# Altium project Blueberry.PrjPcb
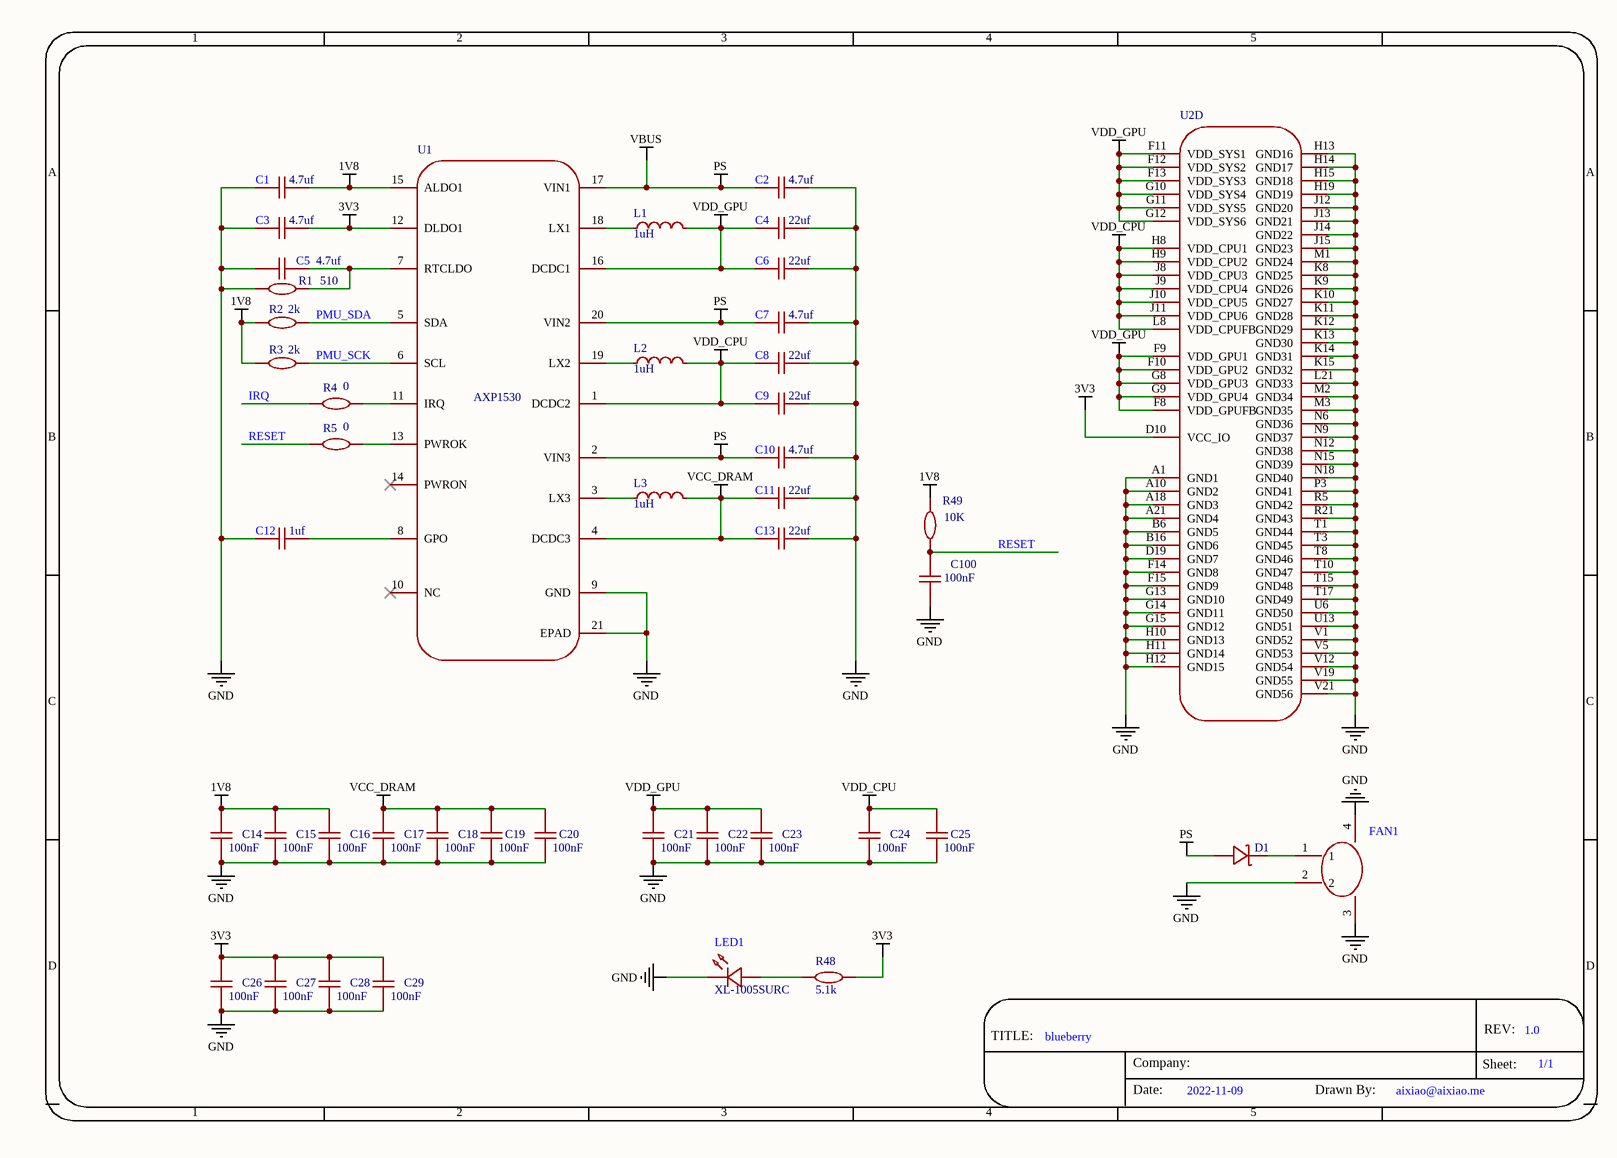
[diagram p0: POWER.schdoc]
4 sheets, 211 parts. Net scope: global (net labels, ports and power ports of the same name join across sheets).
Board file: Blueberry.PcbDoc
Sheets:
  POWER.schdoc
  PLL-IO.schdoc
  DRAM.schdoc
  IO.schdoc

## Sheet POWER.schdoc
size 302 x 215 mm; Symbol: Sheet_A4; Device: Sheet_A4; @Project Name: blueberry; REV: 1.0; Date: 2022-11-09; Sheet: 1/1; Draw By: aixiao@aixiao.me; SheetNumber: 1; SheetTotal: 4

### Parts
C1  value 4.7uf  [C0402-NSK]  (hidden comment: CAP_0402)
C2  value 4.7uf  [C0603 NSK]  (hidden comment: CAP_0603)
C3  value 4.7uf  [C0402-NSK]  (hidden comment: CAP_0402)
C4  value 22uf  [C0603 NSK]  (hidden comment: CAP_0603)
C5  value 4.7uf  [C0402-NSK]  (hidden comment: CAP_0402)
C6  value 22uf  [C0603 NSK]  (hidden comment: CAP_0603)
C7  value 4.7uf  [C0603 NSK]  (hidden comment: CAP_0603)
C8  value 22uf  [C0603 NSK]  (hidden comment: CAP_0603)
C9  value 22uf  [C0603 NSK]  (hidden comment: CAP_0603)
C10  value 4.7uf  [C0603 NSK]  (hidden comment: CAP_0603)
C11  value 22uf  [C0603 NSK]  (hidden comment: CAP_0603)
C12  value 1uf  [C0402-NSK]  (hidden comment: CAP_0402)
C13  value 22uf  [C0603 NSK]  (hidden comment: CAP_0603)
C14  value 100nF  [C0402-NSK]  (hidden comment: CAP_0402)
C15  value 100nF  [C0402-NSK]  (hidden comment: CAP_0402)
C16  value 100nF  [C0402-NSK]  (hidden comment: CAP_0402)
C17  value 100nF  [C0402-NSK]  (hidden comment: CAP_0402)
C18  value 100nF  [C0402-NSK]  (hidden comment: CAP_0402)
C19  value 100nF  [C0402-NSK]  (hidden comment: CAP_0402)
C20  value 100nF  [C0402-NSK]  (hidden comment: CAP_0402)
C21  value 100nF  [C0402-NSK]  (hidden comment: CAP_0402)
C22  value 100nF  [C0402-NSK]  (hidden comment: CAP_0402)
C23  value 100nF  [C0402-NSK]  (hidden comment: CAP_0402)
C24  value 100nF  [C0402-NSK]  (hidden comment: CAP_0402)
C25  value 100nF  [C0402-NSK]  (hidden comment: CAP_0402)
C26  value 100nF  [C0402-NSK]  (hidden comment: CAP_0402)
C27  value 100nF  [C0402-NSK]  (hidden comment: CAP_0402)
C28  value 100nF  [C0402-NSK]  (hidden comment: CAP_0402)
C29  value 100nF  [C0402-NSK]  (hidden comment: CAP_0402)
C100  value 100nF  [C0402-NSK]  (hidden comment: CAP_0402)
D1  B5819WS  [SOD-323_L1.8-W1.3-LS2.5-NSK]  (value not drawn)
FAN1  0533980271  [CONN-SMD_2P-P1.25_053398-0X71]  (value not drawn)
L1  value 1uH  [IND-SMD_L2.0-W1.6_1]  (hidden comment: CKCS201610-2.2uH/M_2)
L2  value 1uH  [IND-SMD_L2.0-W1.6_1]  (hidden comment: CKCS201610-2.2uH/M_2)
L3  value 1uH  [IND-SMD_L2.0-W1.6_1]  (hidden comment: CKCS201610-2.2uH/M_2)
LED1  XL-1005SURC  [LED0402-R-RD_RED]
R1  value 510  [R0402-NSK_2]  (hidden comment: Res_0402)
R2  value 2k  [R0402-NSK_2]  (hidden comment: Res_0402)
R3  value 2k  [R0402-NSK_2]  (hidden comment: Res_0402)
R4  value 0  [R0402-NSK_2]  (hidden comment: Res_0402)
R5  value 0  [R0402-NSK_2]  (hidden comment: Res_0402)
R48  value 5.1k  [R0402-NSK_2]  (hidden comment: Res_0402)
R49  value 10K  [R0402-NSK_2]  (hidden comment: Res_0402)
U1  AXP1530  [WQFN-20_L3.0-W3.0-P0.40-BL-EP]
U2  Allwinner_H616  [BGA284P65B1200_1400H125]  (value not drawn)  (part D of 4)

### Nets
1V8: C1.2 C14.2 C15.2 C16.2 R2.1 R3.1 R49.2 U1.15(ALDO1)
3V3: C3.2 C26.2 C27.2 C28.2 C29.2 R48.2 U1.12(DLDO1) U2.D10(VCC_IO)  [project net VDD33]
GND: C1.1 C2.2 C3.1 C4.2 C5.1 C6.2 C7.2 C8.2 C9.2 C10.2 C11.2 C12.1 C13.2 C14.1 C15.1 C16.1 C17.1 C18.1 C19.1 C20.1 C21.1 C22.1 C23.1 C24.1 C25.1 C26.1 C27.1 C28.1 C29.1 C100.1 FAN1.2 FAN1.3 FAN1.4 LED1.2(A) R1.1 U1.9(GND) U1.21(EPAD) U2.A1(GND1) U2.A10(GND2) U2.A18(GND3) U2.A21(GND4) U2.B6(GND5) U2.B16(GND6) U2.D19(GND7) U2.F14(GND8) U2.F15(GND9) U2.G13(GND10) U2.G14(GND11) U2.G15(GND12) U2.H10(GND13) U2.H11(GND14) U2.H12(GND15) U2.H13(GND16) U2.H14(GND17) U2.H15(GND18) U2.H19(GND19) U2.J12(GND20) U2.J13(GND21) U2.J14(GND22) U2.J15(GND23) U2.K8(GND25) U2.K9(GND26) U2.K10(GND27) U2.K11(GND28) U2.K12(GND29) U2.K13(GND30) U2.K14(GND31) U2.K15(GND32) U2.L21(GND33) U2.M1(GND24) U2.M2(GND34) U2.M3(GND35) U2.N6(GND36) U2.N9(GND37) U2.N12(GND38) U2.N15(GND39) U2.N18(GND40) U2.P3(GND41) U2.R5(GND42) U2.R21(GND43) U2.T1(GND44) U2.T3(GND45) U2.T8(GND46) U2.T10(GND47) U2.T15(GND48) U2.T17(GND49) U2.U6(GND50) U2.U13(GND51) U2.V1(GND52) U2.V5(GND53) U2.V12(GND54) U2.V19(GND55) U2.V21(GND56)
VBUS: C2.1 C7.1 C10.1 D1.2(A) U1.2(VIN3) U1.17(VIN1) U1.20(VIN2)  [also labelled PS]
VCC_DRAM: C11.1 C13.1 C17.2 C18.2 C19.2 C20.2 L3.2 U1.4(DCDC3)
VDD_CPU: C8.1 C9.1 C24.2 C25.2 L2.2 U1.1(DCDC2) U2.H8(VDD_CPU1) U2.H9(VDD_CPU2) U2.J8(VDD_CPU3) U2.J9(VDD_CPU4) U2.J10(VDD_CPU5) U2.J11(VDD_CPU6) U2.L8(VDD_CPUFB)
VDD_GPU: C4.1 C6.1 C21.2 C22.2 C23.2 L1.2 U1.16(DCDC1) U2.F8(VDD_GPUFB) U2.F9(VDD_GPU1) U2.F10(VDD_GPU2) U2.F11(VDD_SYS1) U2.F12(VDD_SYS2) U2.F13(VDD_SYS3) U2.G8(VDD_GPU3) U2.G9(VDD_GPU4) U2.G10(VDD_SYS4) U2.G11(VDD_SYS5) U2.G12(VDD_SYS6)
IRQ: R4.1
PMU_SCK: R3.2 U1.6(SCL)
PMU_SDA: R2.2 U1.5(SDA)
RESET: C100.2 R5.1 R49.1
NetC5_2: C5.2 R1.2 U1.7(RTCLDO)
NetC12_2: C12.2 U1.8(GPO)
NetD1_1: D1.1(K) FAN1.1
NetL1_1: L1.1 U1.18(LX1)
NetL2_1: L2.1 U1.19(LX2)
NetL3_1: L3.1 U1.3(LX3)
NetLED1_1: LED1.1(K) R48.1
NetR4_2: R4.2 U1.11(IRQ)
NetR5_2: R5.2 U1.13(PWROK)

Not connected (* = marked no-connect by the designer): U1 10(NC)* 14(PWRON)*

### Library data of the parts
C1 C3 C5 C12 C14-C29 C100 = CAP_0402: Symbol: C1210X7R475K630NT; Convert to PCB: yes
C2 C4 C6-C11 C13 = CAP_0603: Symbol: C1210X7R475K630NT; Convert to PCB: yes
D1 = B5819WS: Manufacturer: CJ（江苏长电/长晶）; Symbol: B5819WS_C22624; Add into BOM: yes; Reverse Voltage (Vr): 40V; Average Rectified Current (Io): 1A; Forward Voltage (Vf@If): 600mV@1A
FAN1 = 0533980271: Manufacturer: MOLEX; Add into BOM: yes; Pitch: 1.25mm; Pins Structure: 1x2P; Number of PINs Per Row: 2; Gender: 公型插针
L1-L3 = CKCS201610-2.2uH/M_2: Manufacturer: CENKER(岑科); Symbol: CKCS201610-2.2UH/M-N; Add into BOM: yes; Tolerance: ±20%; Rated Current: 1.1A; DC Resistance (DCR): 264mΩ
LED1 = XL-1005SURC: Manufacturer: XINGLIGHT(成兴光); Add into BOM: yes; Emitted Color: 红灯; Lens Color: 无色透明; Dominant Wavelength: 620nm; Peak Wavelength: 625nm; Color Temperature: 6000K~7000K; Forward Current: 25mA; Power Dissipation: 55mW; Viewing Angle: 120°; Mounting Sytle: 正贴
R1-R5 R48 R49 = Res_0402: Symbol: 电阻; Convert to PCB: yes
U1 = AXP1530: Add into BOM: yes; PCB Footprint: QFN21P40B300_300H78
U2 = Allwinner_H616: Symbol: H616-BGA-190823; Convert to PCB: yes

## Sheet PLL-IO.schdoc
size 302 x 215 mm; Symbol: Sheet_A4; Device: Sheet_A4; @Project Name: blueberry; REV: 1.0; Date: 2022-11-09; Sheet: 1/1; Draw By: aixiao@aixiao.me; @Page No: 2; @Page Count: 4; @Schematic Name: blueberry; @Board Name: blueberry; @Update Date: 2024-05-07; @Page Name: PLL-IO; @Create Time: 08:49:38; @Update Time: 11:45:56; @Create Date: 2023-10-26; SheetNumber: 2; SheetTotal: 4
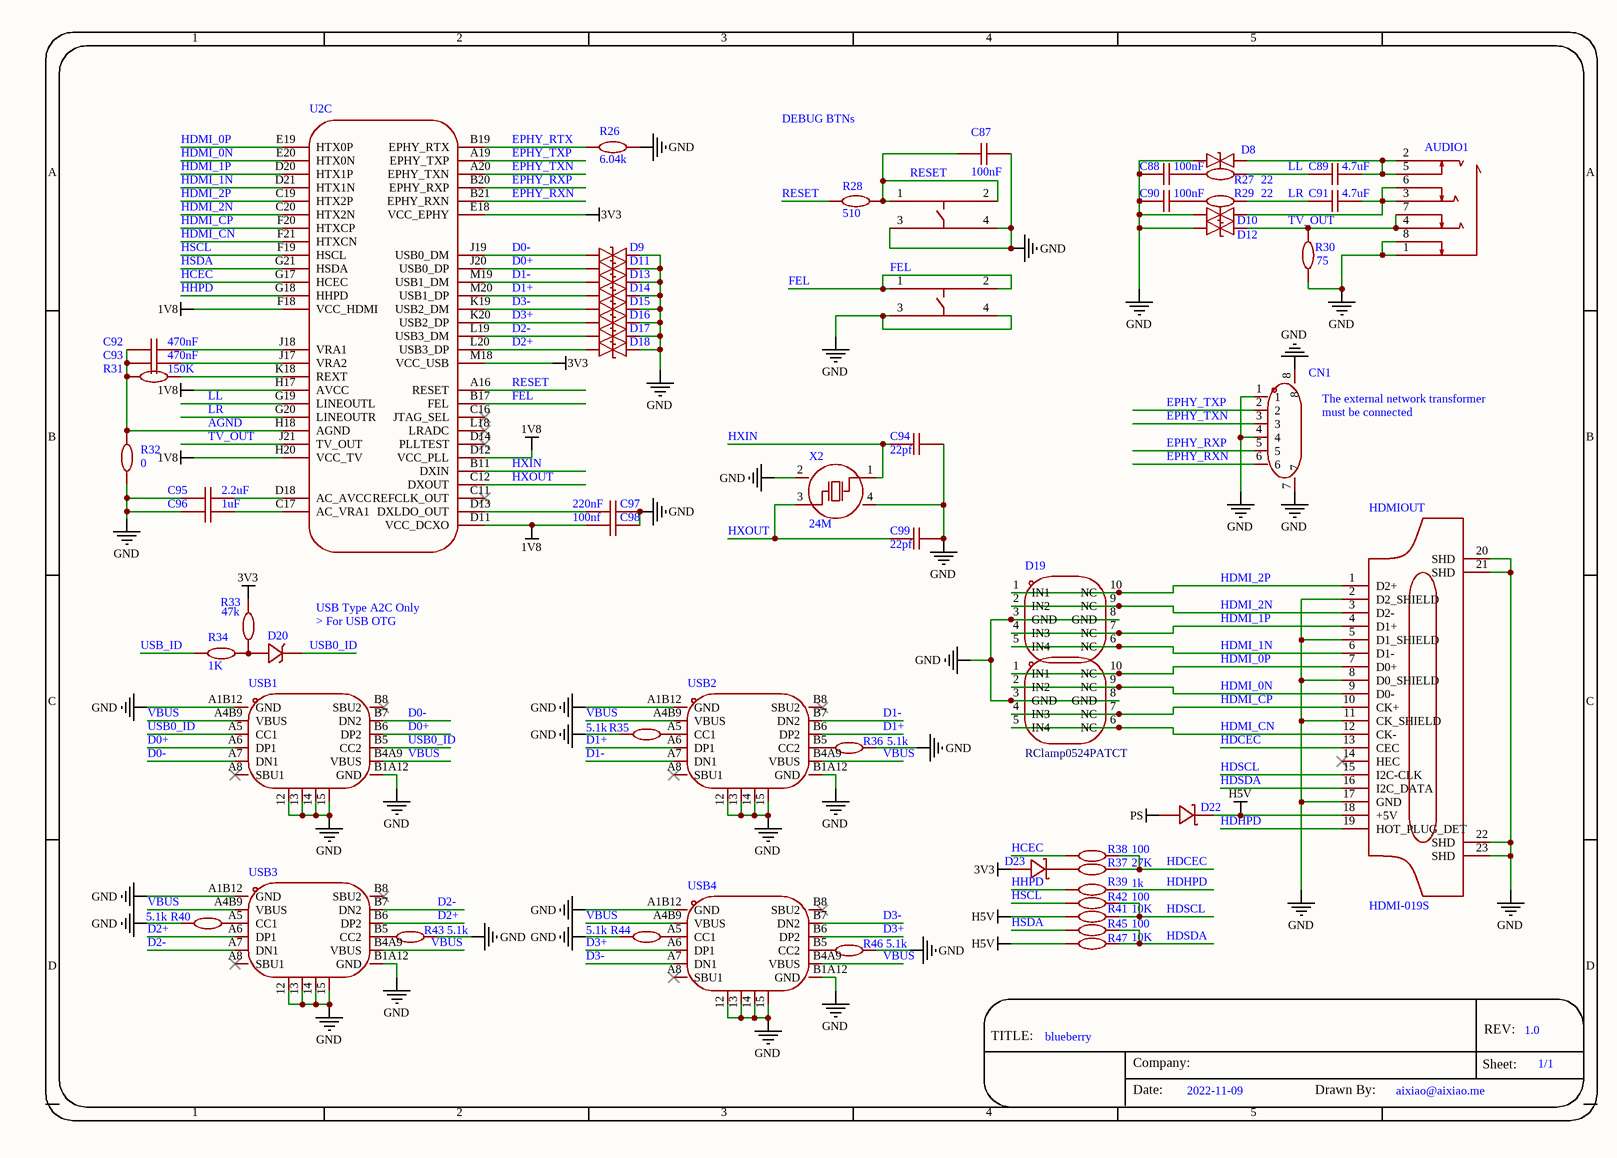
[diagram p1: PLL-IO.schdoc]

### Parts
AUDIO1  PJ-3930-8A  [AUDIO-TH_PJ-3930-8A]  (value not drawn)
C87  value 100nF  [C0402-NSK]  (hidden comment: FN15X104K250PNG)
C88  value 100nF  [C0402-NSK]  (hidden comment: CAP_0402)
C89  value 4.7uF  [C0402-NSK]  (hidden comment: CAP_0402)
C90  value 100nF  [C0402-NSK]  (hidden comment: CAP_0402)
C91  value 4.7uF  [C0402-NSK]  (hidden comment: CAP_0402)
C92  value 470nF  [C0402-NSK]  (hidden comment: CAP_0402)
C93  value 470nF  [C0402-NSK]  (hidden comment: CAP_0402)
C94  value 22pf  [C0402-NSK]  (hidden comment: CAP_0402)
C95  value 2.2uF  [C0402-NSK]  (hidden comment: CAP_0402)
C96  value 1uF  [C0402-NSK]  (hidden comment: CAP_0402)
C97  value 220nF  [C0402-NSK]  (hidden comment: CAP_0402)
C98  value 100nf  [C0402-NSK]  (hidden comment: CAP_0402)
C99  value 22pf  [C0402-NSK]  (hidden comment: CAP_0402)
CN1  532610671  [CONN-SMD_6P-P1.25_53261-0671]  (value not drawn)
D8  0402ESDA-05N  [D0402]  (value not drawn)
D9  0402ESDA-05N  [D0402]  (value not drawn)
D10  0402ESDA-05N  [D0402]  (value not drawn)
D11  0402ESDA-05N  [D0402]  (value not drawn)
D12  0402ESDA-05N  [D0402]  (value not drawn)
D13  0402ESDA-05N  [D0402]  (value not drawn)
D14  0402ESDA-05N  [D0402]  (value not drawn)
D15  0402ESDA-05N  [D0402]  (value not drawn)
D16  0402ESDA-05N  [D0402]  (value not drawn)
D17  0402ESDA-05N  [D0402]  (value not drawn)
D18  0402ESDA-05N  [D0402]  (value not drawn)
D19  RClamp0524PATCT  [SLP2510P8_L2.5-W1.0-P0.50-BL]
D20  1N5819-SOD523  [SOD-523_L1.2-W0.8-LS1.6-FD]  (value not drawn)
D21  RClamp0524PATCT  [SLP2510P8_L2.5-W1.0-P0.50-BL]  (value not drawn)
D22  B5819WS  [SOD-323_L1.8-W1.3-LS2.5-NSK]  (value not drawn)
D23  B5819WS  [SOD-323_L1.8-W1.3-LS2.5-NSK]  (value not drawn)
FEL  PTS810SJM250SMTRLFS  [KEY-SMD_4P-L4.2-W3.2-P2.20-LS4.6]  (value not drawn)
HDMIOUT  HDMI-019S  [HDMI-SMD_HDMI-019S]
R26  value 6.04k  [R0402-NSK_2]  (hidden comment: Res_0402)
R27  value 22  [R0402-NSK_2]  (hidden comment: Res_0402)
R28  value 510  [R0402-NSK_2]  (hidden comment: TR0402D10K0Q1025Z)
R29  value 22  [R0402-NSK_2]  (hidden comment: Res_0402)
R30  value 75  [R0402-NSK_2]  (hidden comment: Res_0402)
R31  value 150K  [R0402-NSK_2]  (hidden comment: Res_0402)
R32  value 0  [R0402-NSK_2]  (hidden comment: Res_0402)
R33  value 47k  [R0402-NSK_2]  (hidden comment: Res_0402)
R34  value 1K  [R0402-NSK_2]  (hidden comment: Res_0402)
R35  value 5.1k  [R0402-NSK_2]  (hidden comment: Res_0402)
R36  value 5.1k  [R0402-NSK_2]  (hidden comment: Res_0402)
R37  value 27K  [R0402-NSK_2]  (hidden comment: Res_0402)
R38  value 100  [R0402-NSK_2]  (hidden comment: Res_0402)
R39  value 1k  [R0402-NSK_2]  (hidden comment: Res_0402)
R40  value 5.1k  [R0402-NSK_2]  (hidden comment: Res_0402)
R41  value 10K  [R0402-NSK_2]  (hidden comment: Res_0402)
R42  value 100  [R0402-NSK_2]  (hidden comment: Res_0402)
R43  value 5.1k  [R0402-NSK_2]  (hidden comment: Res_0402)
R44  value 5.1k  [R0402-NSK_2]  (hidden comment: Res_0402)
R45  value 100  [R0402-NSK_2]  (hidden comment: Res_0402)
R46  value 5.1k  [R0402-NSK_2]  (hidden comment: Res_0402)
R47  value 10K  [R0402-NSK_2]  (hidden comment: Res_0402)
RESET  PTS810SJM250SMTRLFS  [KEY-SMD_4P-L4.2-W3.2-P2.20-LS4.6]  (value not drawn)
U2  Allwinner_H616  [BGA284P65B1200_1400H125]  (value not drawn)  (part C of 4)
USB1  TYPEC-304-BCP16  [USB-C-SMD_TYPEC-304-BCP16-1]  (value not drawn)
USB2  TYPEC-304-BCP16  [USB-C-SMD_TYPEC-304-BCP16-1]  (value not drawn)
USB3  TYPEC-304-BCP16  [USB-C-SMD_TYPEC-304-BCP16-1]  (value not drawn)
USB4  TYPEC-304-BCP16  [USB-C-SMD_TYPEC-304-BCP16-1]  (value not drawn)
X2  24M  [OSC-SMD_4P-L2.0-W1.6-BL]

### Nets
1V8: C98.1 U2.D11(VCC_DCXO) U2.D12(VCC_PLL) U2.F18(VCC_HDMI) U2.H17(AVCC) U2.H20(VCC_TV)
3V3: D23.2(A) R33.2 U2.E18(VCC_EPHY) U2.M18(VCC_USB)  [project net VDD33]
GND: AUDIO1.1 AUDIO1.8 C87.2 C88.1 C90.1 C94.2 C95.1 C96.1 C97.2 C98.2 C99.2 CN1.1 CN1.4 CN1.7 CN1.8 D8.1 D9.2 D10.1 D11.2 D12.1 D13.2 D14.2 D15.2 D16.2 D17.2 D18.2 D19.3(GND) D19.8(GND) D21.3(GND) D21.8(GND) FEL.3 FEL.4 HDMIOUT.2(D2_SHIELD) HDMIOUT.5(D1_SHIELD) HDMIOUT.8(D0_SHIELD) HDMIOUT.11(CK_SHIELD) HDMIOUT.17(GND) HDMIOUT.20(SHD) HDMIOUT.21(SHD) HDMIOUT.22(SHD) HDMIOUT.23(SHD) R26.2 R30.1 R32.1 R35.1 R36.2 R40.1 R43.2 R44.1 R46.2 RESET.3 RESET.4 USB1.12 USB1.13 USB1.14 USB1.15 USB1.A1B12(GND) USB1.B1A12(GND) USB2.12 USB2.13 USB2.14 USB2.15 USB2.A1B12(GND) USB2.B1A12(GND) USB3.12 USB3.13 USB3.14 USB3.15 USB3.A1B12(GND) USB3.B1A12(GND) USB4.12 USB4.13 USB4.14 USB4.15 USB4.A1B12(GND) USB4.B1A12(GND) X2.2(GND) X2.4(GND)
H5V: D22.1(K) HDMIOUT.18(+5V) R41.1 R47.1
VBUS: D22.2(A) USB1.A4B9(VBUS) USB1.B4A9(VBUS) USB2.A4B9(VBUS) USB2.B4A9(VBUS) USB3.A4B9(VBUS) USB3.B4A9(VBUS) USB4.A4B9(VBUS) USB4.B4A9(VBUS)  [also labelled PS]
AGND: C92.1 C93.1 R31.1 R32.2 U2.H18(AGND)
D0+: D11.1 U2.J20(USB0_DP) USB1.A6(DP1) USB1.B6(DP2)
D0-: D9.1 U2.J19(USB0_DM) USB1.A7(DN1) USB1.B7(DN2)
D1+: D14.1 U2.M20(USB1_DP) USB2.A6(DP1) USB2.B6(DP2)
D1-: D13.1 U2.M19(USB1_DM) USB2.A7(DN1) USB2.B7(DN2)
D2+: D18.1 U2.L20(USB3_DP) USB3.A6(DP1) USB3.B6(DP2)
D2-: D17.1 U2.L19(USB3_DM) USB3.A7(DN1) USB3.B7(DN2)
D3+: D16.1 U2.K20(USB2_DP) USB4.A6(DP1) USB4.B6(DP2)
D3-: D15.1 U2.K19(USB2_DM) USB4.A7(DN1) USB4.B7(DN2)
EPHY_RTX: R26.1 U2.B19(EPHY_RTX)
EPHY_RXN: CN1.6 U2.B21(EPHY_RXN)
EPHY_RXP: CN1.5 U2.B20(EPHY_RXP)
EPHY_TXN: CN1.3 U2.A20(EPHY_TXN)
EPHY_TXP: CN1.2 U2.A19(EPHY_TXP)
FEL: FEL.1 FEL.2 U2.B17(FEL)
HCEC: R38.1 U2.G17(HCEC)
HDCEC: HDMIOUT.13(CEC) R37.2 R38.2
HDHPD: HDMIOUT.19(HOT_PLUG_DET) R39.2
HDMI_0N: D21.2(IN2) D21.9(NC) HDMIOUT.9(D0-) U2.E20(HTX0N)
HDMI_0P: D21.1(IN1) D21.10(NC) HDMIOUT.7(D0+) U2.E19(HTX0P)
HDMI_1N: D19.5(IN4) D19.6(NC) HDMIOUT.6(D1-) U2.D21(HTX1N)
HDMI_1P: D19.4(IN3) D19.7(NC) HDMIOUT.4(D1+) U2.D20(HTX1P)
HDMI_2N: D19.2(IN2) D19.9(NC) HDMIOUT.3(D2-) U2.C20(HTX2N)
HDMI_2P: D19.1(IN1) D19.10(NC) HDMIOUT.1(D2+) U2.C19(HTX2P)
HDMI_CN: D21.5(IN4) D21.6(NC) HDMIOUT.12(CK-) U2.F21(HTXCN)
HDMI_CP: D21.4(IN3) D21.7(NC) HDMIOUT.10(CK+) U2.F20(HTXCP)
HDSCL: HDMIOUT.15(I2C-CLK) R41.2 R42.2
HDSDA: HDMIOUT.16(I2C_DATA) R45.2 R47.2
HHPD: R39.1 U2.G18(HHPD)
HSCL: R42.1 U2.F19(HSCL)
HSDA: R45.1 U2.G21(HSDA)
HXIN: C94.1 U2.B11(DXIN) X2.1(OSC1)
HXOUT: C99.1 U2.C12(DXOUT) X2.3(OSC2)
LL: C89.1 R27.2 U2.G19(LINEOUTL)
LR: C91.1 R29.2 U2.G20(LINEOUTR)
RESET: R28.1 U2.A16(RESET)
TV_OUT: AUDIO1.4 AUDIO1.7 D12.2 R30.2 U2.J21(TV_OUT)
USB0_ID: D20.2(K) USB1.A5(CC1) USB1.B5(CC2)
USB_ID: R34.1
NetAUDIO1_2: AUDIO1.2 AUDIO1.5 C89.2 D8.2
NetAUDIO1_3: AUDIO1.3 AUDIO1.6 C91.2 D10.2
NetC87_1: C87.1 R28.2 RESET.1 RESET.2
NetC88_2: C88.2 R27.1
NetC90_2: C90.2 R29.1
NetC92_2: C92.2 U2.J18(VRA1)
NetC93_2: C93.2 U2.J17(VRA2)
NetC95_2: C95.2 U2.D18(AC_AVCC)
NetC96_2: C96.2 U2.C17(AC_VRA1)
NetC97_1: C97.1 U2.D13(DXLDO_OUT)
NetD20_1: D20.1(A) R33.1 R34.2
NetD23_1: D23.1(K) R37.1
NetR31_2: R31.2 U2.K18(REXT)
NetR35_2: R35.2 USB2.A5(CC1)
NetR36_1: R36.1 USB2.B5(CC2)
NetR40_2: R40.2 USB3.A5(CC1)
NetR43_1: R43.1 USB3.B5(CC2)
NetR44_2: R44.2 USB4.A5(CC1)
NetR46_1: R46.1 USB4.B5(CC2)

Not connected (* = marked no-connect by the designer): HDMIOUT 14(HEC)*; U2 C11(REFCLK_OUT)* C16(JTAG_SEL)* D14(PLLTEST)* L18(LRADC)*; USB1 A8(SBU1)* B8(SBU2)*; USB2 A8(SBU1)* B8(SBU2)*; USB3 A8(SBU1)* B8(SBU2)*; USB4 A8(SBU1)* B8(SBU2)*

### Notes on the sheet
- DEBUG BTNs
- The external network transformer
  must be connected
- (near USB1) USB Type A2C Only
  > For USB OTG

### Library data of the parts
AUDIO1 = PJ-3930-8A: Manufacturer: 韩国韩荣; Add into BOM: yes; Connector Type: 3.5mm耳机座; Current Rating (Max): 500mA; Voltage Rating (Max): 30V
C87 = FN15X104K250PNG: Manufacturer: PSA(信昌电陶); Add into BOM: yes; Tolerance: ±10%; Voltage Rated: 25V; Temperature Coefficient: X7R
C88-C99 = CAP_0402: as C1 on sheet POWER
CN1 = 532610671: Manufacturer: MOLEX; Symbol: 53261-0671; Add into BOM: yes; Pitch: 1.25mm; Pins Structure: 1x6P; Number of PINs Per Row: 6
D8-D18 = 0402ESDA-05N: Manufacturer: BORN伯恩半导体; Add into BOM: yes; Polarity: Bidirectional; Voltage - Reverse Standoff (Typ): 5V; Voltage - Clamping (Max) @ Ipp: 50V
D19 D21 = RClamp0524PATCT: Manufacturer: SEMTECH; Add into BOM: yes
D20 = 1N5819-SOD523: Add into BOM: yes
D22 D23 = B5819WS: as D1 on sheet POWER
FEL RESET = PTS810SJM250SMTRLFS: Manufacturer: C&K; Add into BOM: yes; Contact Current: 50mA; Voltage Rating (DC): 16V; Circuit: 单刀单掷; Actuator Style: 圆形按钮; Operating Force: 160gf; Pin Style: J型引脚; Switch Length: 4.2mm; Switch Width: 3.2mm; Switch Height: 2.5mm
HDMIOUT = HDMI-019S: Manufacturer: SOFNG(硕方); Add into BOM: yes; Connector Type: HDMI; Gender: 母; Current Rating (Max): 500mA
R26 R27 R29-R47 = Res_0402: Symbol: 电阻; Convert to PCB: yes
R28 = TR0402D10K0Q1025Z: Manufacturer: EVER OHMS(天二科技); Symbol: TR0402D10KQ1025; Add into BOM: yes; Tolerance: ±0.5%; Power(Watts): 63mW; Temperature Coefficient: ±25ppm/; Overload Voltage (Max): 25V
U2 = Allwinner_H616: as U2 on sheet POWER
USB1-USB4 = TYPEC-304-BCP16: Manufacturer: XUNPU; Pin Type: IN; Add into BOM: yes
X2 = SX32Y024000BC1T: Manufacturer: TKD(泰晶); Add into BOM: yes

## Sheet DRAM.schdoc
size 302 x 215 mm; Symbol: Sheet_A4; Device: Sheet_A4; @Project Name: blueberry; REV: 1.0; Date: 2022-11-09; Sheet: 1/1; Draw By: aixiao@aixiao.me; SheetNumber: 3; SheetTotal: 4
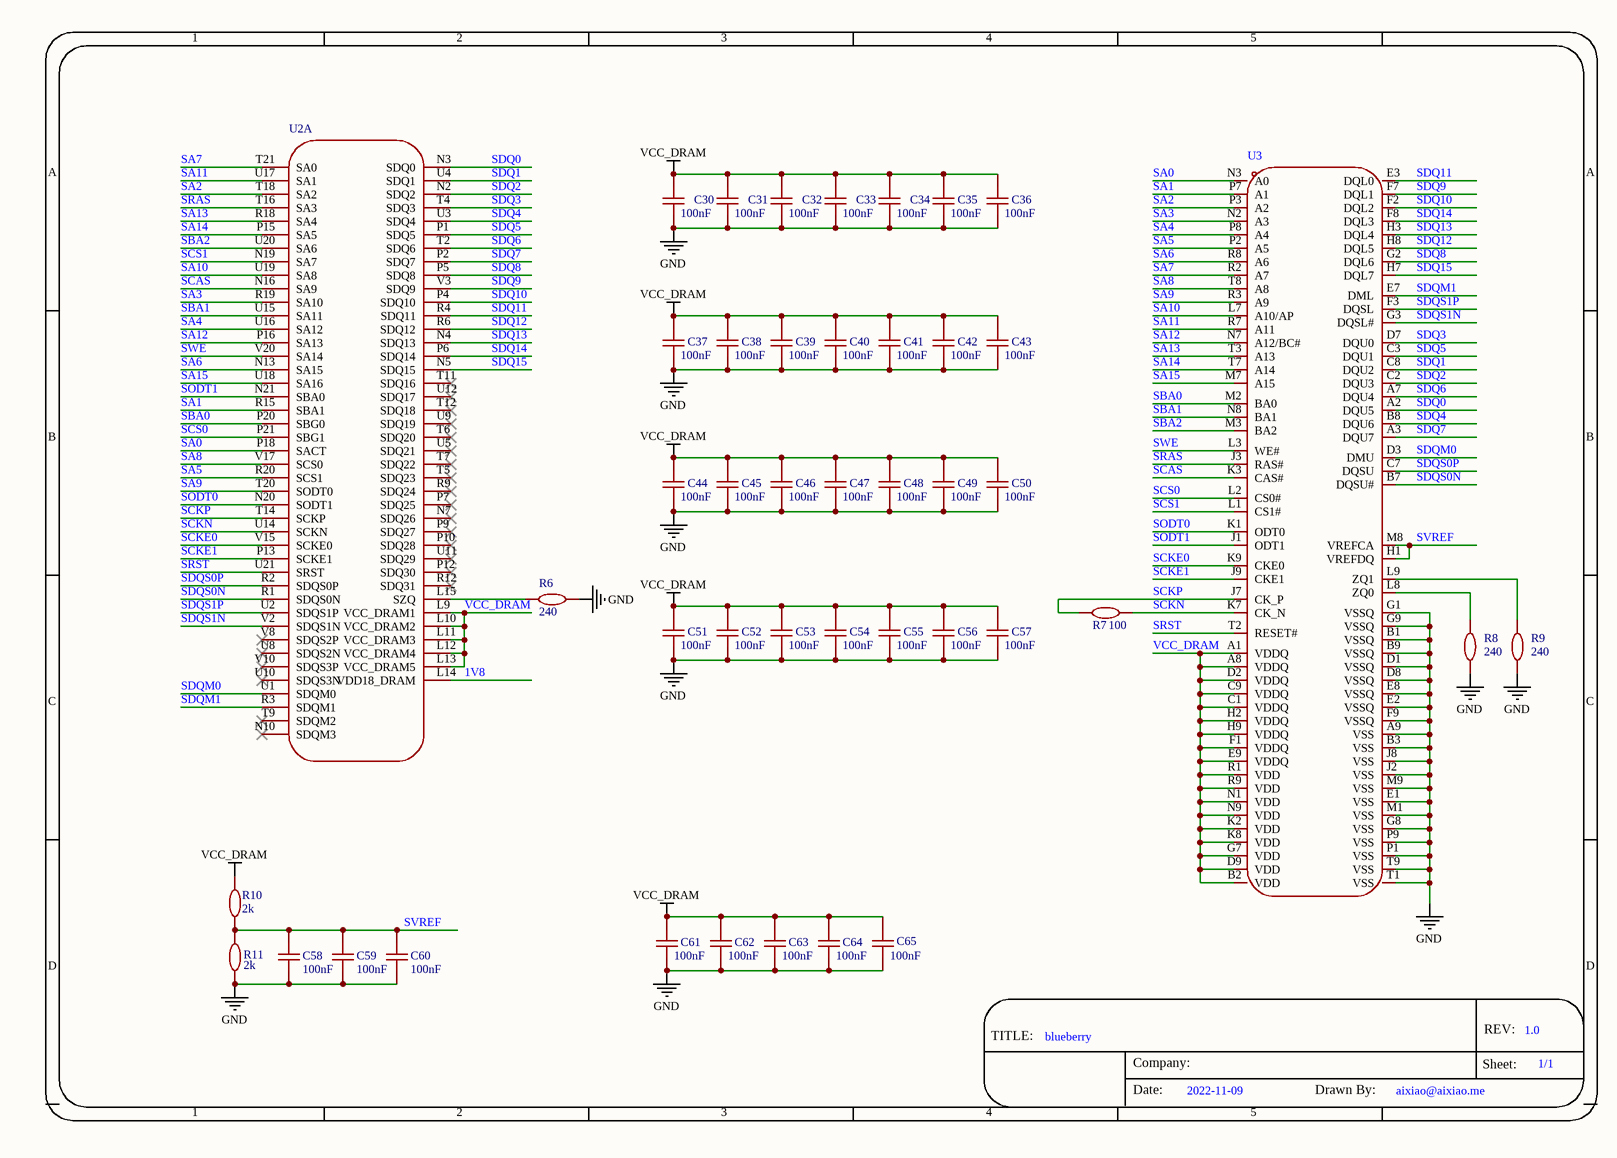
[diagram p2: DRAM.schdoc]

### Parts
C30  value 100nF  [C0402-NSK]  (hidden comment: CAP_0402)
C31  value 100nF  [C0402-NSK]  (hidden comment: CAP_0402)
C32  value 100nF  [C0402-NSK]  (hidden comment: CAP_0402)
C33  value 100nF  [C0402-NSK]  (hidden comment: CAP_0402)
C34  value 100nF  [C0402-NSK]  (hidden comment: CAP_0402)
C35  value 100nF  [C0402-NSK]  (hidden comment: CAP_0402)
C36  value 100nF  [C0402-NSK]  (hidden comment: CAP_0402)
C37  value 100nF  [C0402-NSK]  (hidden comment: CAP_0402)
C38  value 100nF  [C0402-NSK]  (hidden comment: CAP_0402)
C39  value 100nF  [C0402-NSK]  (hidden comment: CAP_0402)
C40  value 100nF  [C0402-NSK]  (hidden comment: CAP_0402)
C41  value 100nF  [C0402-NSK]  (hidden comment: CAP_0402)
C42  value 100nF  [C0402-NSK]  (hidden comment: CAP_0402)
C43  value 100nF  [C0402-NSK]  (hidden comment: CAP_0402)
C44  value 100nF  [C0402-NSK]  (hidden comment: CAP_0402)
C45  value 100nF  [C0402-NSK]  (hidden comment: CAP_0402)
C46  value 100nF  [C0402-NSK]  (hidden comment: CAP_0402)
C47  value 100nF  [C0402-NSK]  (hidden comment: CAP_0402)
C48  value 100nF  [C0402-NSK]  (hidden comment: CAP_0402)
C49  value 100nF  [C0402-NSK]  (hidden comment: CAP_0402)
C50  value 100nF  [C0402-NSK]  (hidden comment: CAP_0402)
C51  value 100nF  [C0402-NSK]  (hidden comment: CAP_0402)
C52  value 100nF  [C0402-NSK]  (hidden comment: CAP_0402)
C53  value 100nF  [C0402-NSK]  (hidden comment: CAP_0402)
C54  value 100nF  [C0402-NSK]  (hidden comment: CAP_0402)
C55  value 100nF  [C0402-NSK]  (hidden comment: CAP_0402)
C56  value 100nF  [C0402-NSK]  (hidden comment: CAP_0402)
C57  value 100nF  [C0402-NSK]  (hidden comment: CAP_0402)
C58  value 100nF  [C0402-NSK]  (hidden comment: CAP_0402)
C59  value 100nF  [C0402-NSK]  (hidden comment: CAP_0402)
C60  value 100nF  [C0402-NSK]  (hidden comment: CAP_0402)
C61  value 100nF  [C0402-NSK]  (hidden comment: CAP_0402)
C62  value 100nF  [C0402-NSK]  (hidden comment: CAP_0402)
C63  value 100nF  [C0402-NSK]  (hidden comment: CAP_0402)
C64  value 100nF  [C0402-NSK]  (hidden comment: CAP_0402)
C65  value 100nF  [C0402-NSK]  (hidden comment: CAP_0402)
R6  value 240  [R0402-NSK_2]  (hidden comment: Res_0402)
R7  value 100  [R0402-NSK_2]  (hidden comment: Res_0402)
R8  value 240  [R0402-NSK_2]  (hidden comment: Res_0402)
R9  value 240  [R0402-NSK_2]  (hidden comment: Res_0402)
R10  value 2k  [R0402-NSK_2]  (hidden comment: Res_0402)
R11  value 2k  [R0402-NSK_2]  (hidden comment: Res_0402)
U2  Allwinner_H616  [BGA284P65B1200_1400H125]  (value not drawn)  (part A of 4)
U3  H5TQ4G63EFR-RDC  [FBGA96]  (value not drawn)

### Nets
1V8: U2.L14(VDD18_DRAM)
GND: C30.1 C31.1 C32.1 C33.1 C34.1 C35.1 C36.1 C37.1 C38.1 C39.1 C40.1 C41.1 C42.1 C43.1 C44.1 C45.1 C46.1 C47.1 C48.1 C49.1 C50.1 C51.1 C52.1 C53.1 C54.1 C55.1 C56.1 C57.1 C58.1 C59.1 C60.1 C61.1 C62.1 C63.1 C64.1 C65.1 R6.2 R8.1 R9.1 R11.1 U3.A9(VSS) U3.B1(VSSQ) U3.B3(VSS) U3.B9(VSSQ) U3.D1(VSSQ) U3.D8(VSSQ) U3.E1(VSS) U3.E2(VSSQ) U3.E8(VSSQ) U3.F9(VSSQ) U3.G1(VSSQ) U3.G8(VSS) U3.G9(VSSQ) U3.J2(VSS) U3.J8(VSS) U3.M1(VSS) U3.M9(VSS) U3.P1(VSS) U3.P9(VSS) U3.T1(VSS) U3.T9(VSS)
VCC_DRAM: C30.2 C31.2 C32.2 C33.2 C34.2 C35.2 C36.2 C37.2 C38.2 C39.2 C40.2 C41.2 C42.2 C43.2 C44.2 C45.2 C46.2 C47.2 C48.2 C49.2 C50.2 C51.2 C52.2 C53.2 C54.2 C55.2 C56.2 C57.2 C61.2 C62.2 C63.2 C64.2 C65.2 R10.2 U2.L9(VCC_DRAM1) U2.L10(VCC_DRAM2) U2.L11(VCC_DRAM3) U2.L12(VCC_DRAM4) U2.L13(VCC_DRAM5) U3.A1(VDDQ) U3.A8(VDDQ) U3.B2(VDD) U3.C1(VDDQ) U3.C9(VDDQ) U3.D2(VDDQ) U3.D9(VDD) U3.E9(VDDQ) U3.F1(VDDQ) U3.G7(VDD) U3.H2(VDDQ) U3.H9(VDDQ) U3.K2(VDD) U3.K8(VDD) U3.N1(VDD) U3.N9(VDD) U3.R1(VDD) U3.R9(VDD)
SA0: U2.P18(SACT) U3.N3(A0)
SA1: U2.R15(SBA1) U3.P7(A1)
SA2: U2.T18(SA2) U3.P3(A2)
SA3: U2.R19(SA10) U3.N2(A3)
SA4: U2.U16(SA12) U3.P8(A4)
SA5: U2.R20(SCS1) U3.P2(A5)
SA6: U2.N13(SA15) U3.R8(A6)
SA7: U2.T21(SA0) U3.R2(A7)
SA8: U2.V17(SCS0) U3.T8(A8)
SA9: U2.T20(SODT0) U3.R3(A9)
SA10: U2.U19(SA8) U3.L7(A10/AP)
SA11: U2.U17(SA1) U3.R7(A11)
SA12: U2.P16(SA13) U3.N7(A12/BC#)
SA13: U2.R18(SA4) U3.T3(A13)
SA14: U2.P15(SA5) U3.T7(A14)
SA15: U2.U18(SA16) U3.M7(A15)
SBA0: U2.P20(SBG0) U3.M2(BA0)
SBA1: U2.U15(SA11) U3.N8(BA1)
SBA2: U2.U20(SA6) U3.M3(BA2)
SCAS: U2.N16(SA9) U3.K3(CAS#)
SCKE0: U2.V15(SCKE0) U3.K9(CKE0)
SCKE1: U2.P13(SCKE1) U3.J9(CKE1)
SCKN: R7.2 U2.U14(SCKN) U3.K7(CK_N)
SCKP: R7.1 U2.T14(SCKP) U3.J7(CK_P)
SCS0: U2.P21(SBG1) U3.L2(CS0#)
SCS1: U2.N19(SA7) U3.L1(CS1#)
SDQ0: U2.N3(SDQ0) U3.A2(DQU5)
SDQ1: U2.U4(SDQ1) U3.C8(DQU2)
SDQ2: U2.N2(SDQ2) U3.C2(DQU3)
SDQ3: U2.T4(SDQ3) U3.D7(DQU0)
SDQ4: U2.U3(SDQ4) U3.B8(DQU6)
SDQ5: U2.P1(SDQ5) U3.C3(DQU1)
SDQ6: U2.T2(SDQ6) U3.A7(DQU4)
SDQ7: U2.P2(SDQ7) U3.A3(DQU7)
SDQ8: U2.P5(SDQ8) U3.G2(DQL6)
SDQ9: U2.V3(SDQ9) U3.F7(DQL1)
SDQ10: U2.P4(SDQ10) U3.F2(DQL2)
SDQ11: U2.R4(SDQ11) U3.E3(DQL0)
SDQ12: U2.R6(SDQ12) U3.H8(DQL5)
SDQ13: U2.N4(SDQ13) U3.H3(DQL4)
SDQ14: U2.P6(SDQ14) U3.F8(DQL3)
SDQ15: U2.N5(SDQ15) U3.H7(DQL7)
SDQM0: U2.U1(SDQM0) U3.D3(DMU)
SDQM1: U2.R3(SDQM1) U3.E7(DML)
SDQS0N: U2.R1(SDQS0N) U3.B7(DQSU#)
SDQS0P: U2.R2(SDQS0P) U3.C7(DQSU)
SDQS1N: U2.V2(SDQS1N) U3.G3(DQSL#)
SDQS1P: U2.U2(SDQS1P) U3.F3(DQSL)
SODT0: U2.N20(SODT1) U3.K1(ODT0)
SODT1: U2.N21(SBA0) U3.J1(ODT1)
SRAS: U2.T16(SA3) U3.J3(RAS#)
SRST: U2.U21(SRST) U3.T2(RESET#)
SVREF: C58.2 C59.2 C60.2 R10.1 R11.2 U3.H1(VREFDQ) U3.M8(VREFCA)
SWE: U2.V20(SA14) U3.L3(WE#)
NetR6_1: R6.1 U2.L15(SZQ)
NetR8_2: R8.2 U3.L8(ZQ0)
NetR9_2: R9.2 U3.L9(ZQ1)

Not connected (* = marked no-connect by the designer): U2 N7(SDQ26)* N10(SDQM3)* P7(SDQ25)* P9(SDQ27)* P10(SDQ28)* P12(SDQ30)* R9(SDQ24)* R12(SDQ31)* T5(SDQ23)* T6(SDQ20)* T7(SDQ22)* T9(SDQM2)* T11(SDQ16)* T12(SDQ18)* U5(SDQ21)* U8(SDQS2N)* U9(SDQ19)* U10(SDQS3N)* U11(SDQ29)* U12(SDQ17)* V8(SDQS2P)* V10(SDQS3P)*

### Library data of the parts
C30-C65 = CAP_0402: as C1 on sheet POWER
R6-R11 = Res_0402: Symbol: 电阻; Convert to PCB: yes
U2 = Allwinner_H616: as U2 on sheet POWER
U3 = H5TQ4G63EFR-RDC: Manufacturer: HYNIX(海力士); Pin Type: IN; Add into BOM: yes

## Sheet IO.schdoc
size 429 x 307 mm; Symbol: Sheet_A3; Device: Sheet_A3; @Project Name: blueberry; REV: 1.0; Date: 2022-11-09; Sheet: 1/1; Draw By: aixiao@aixiao.me; @Page No: 4; @Page Count: 4; @Schematic Name: blueberry; @Board Name: blueberry; @Update Date: 2023-12-25; @Page Name: IO; @Create Time: 08:49:38; @Update Time: 15:31:42; @Create Date: 2023-10-26; SheetNumber: 4; SheetTotal: 4
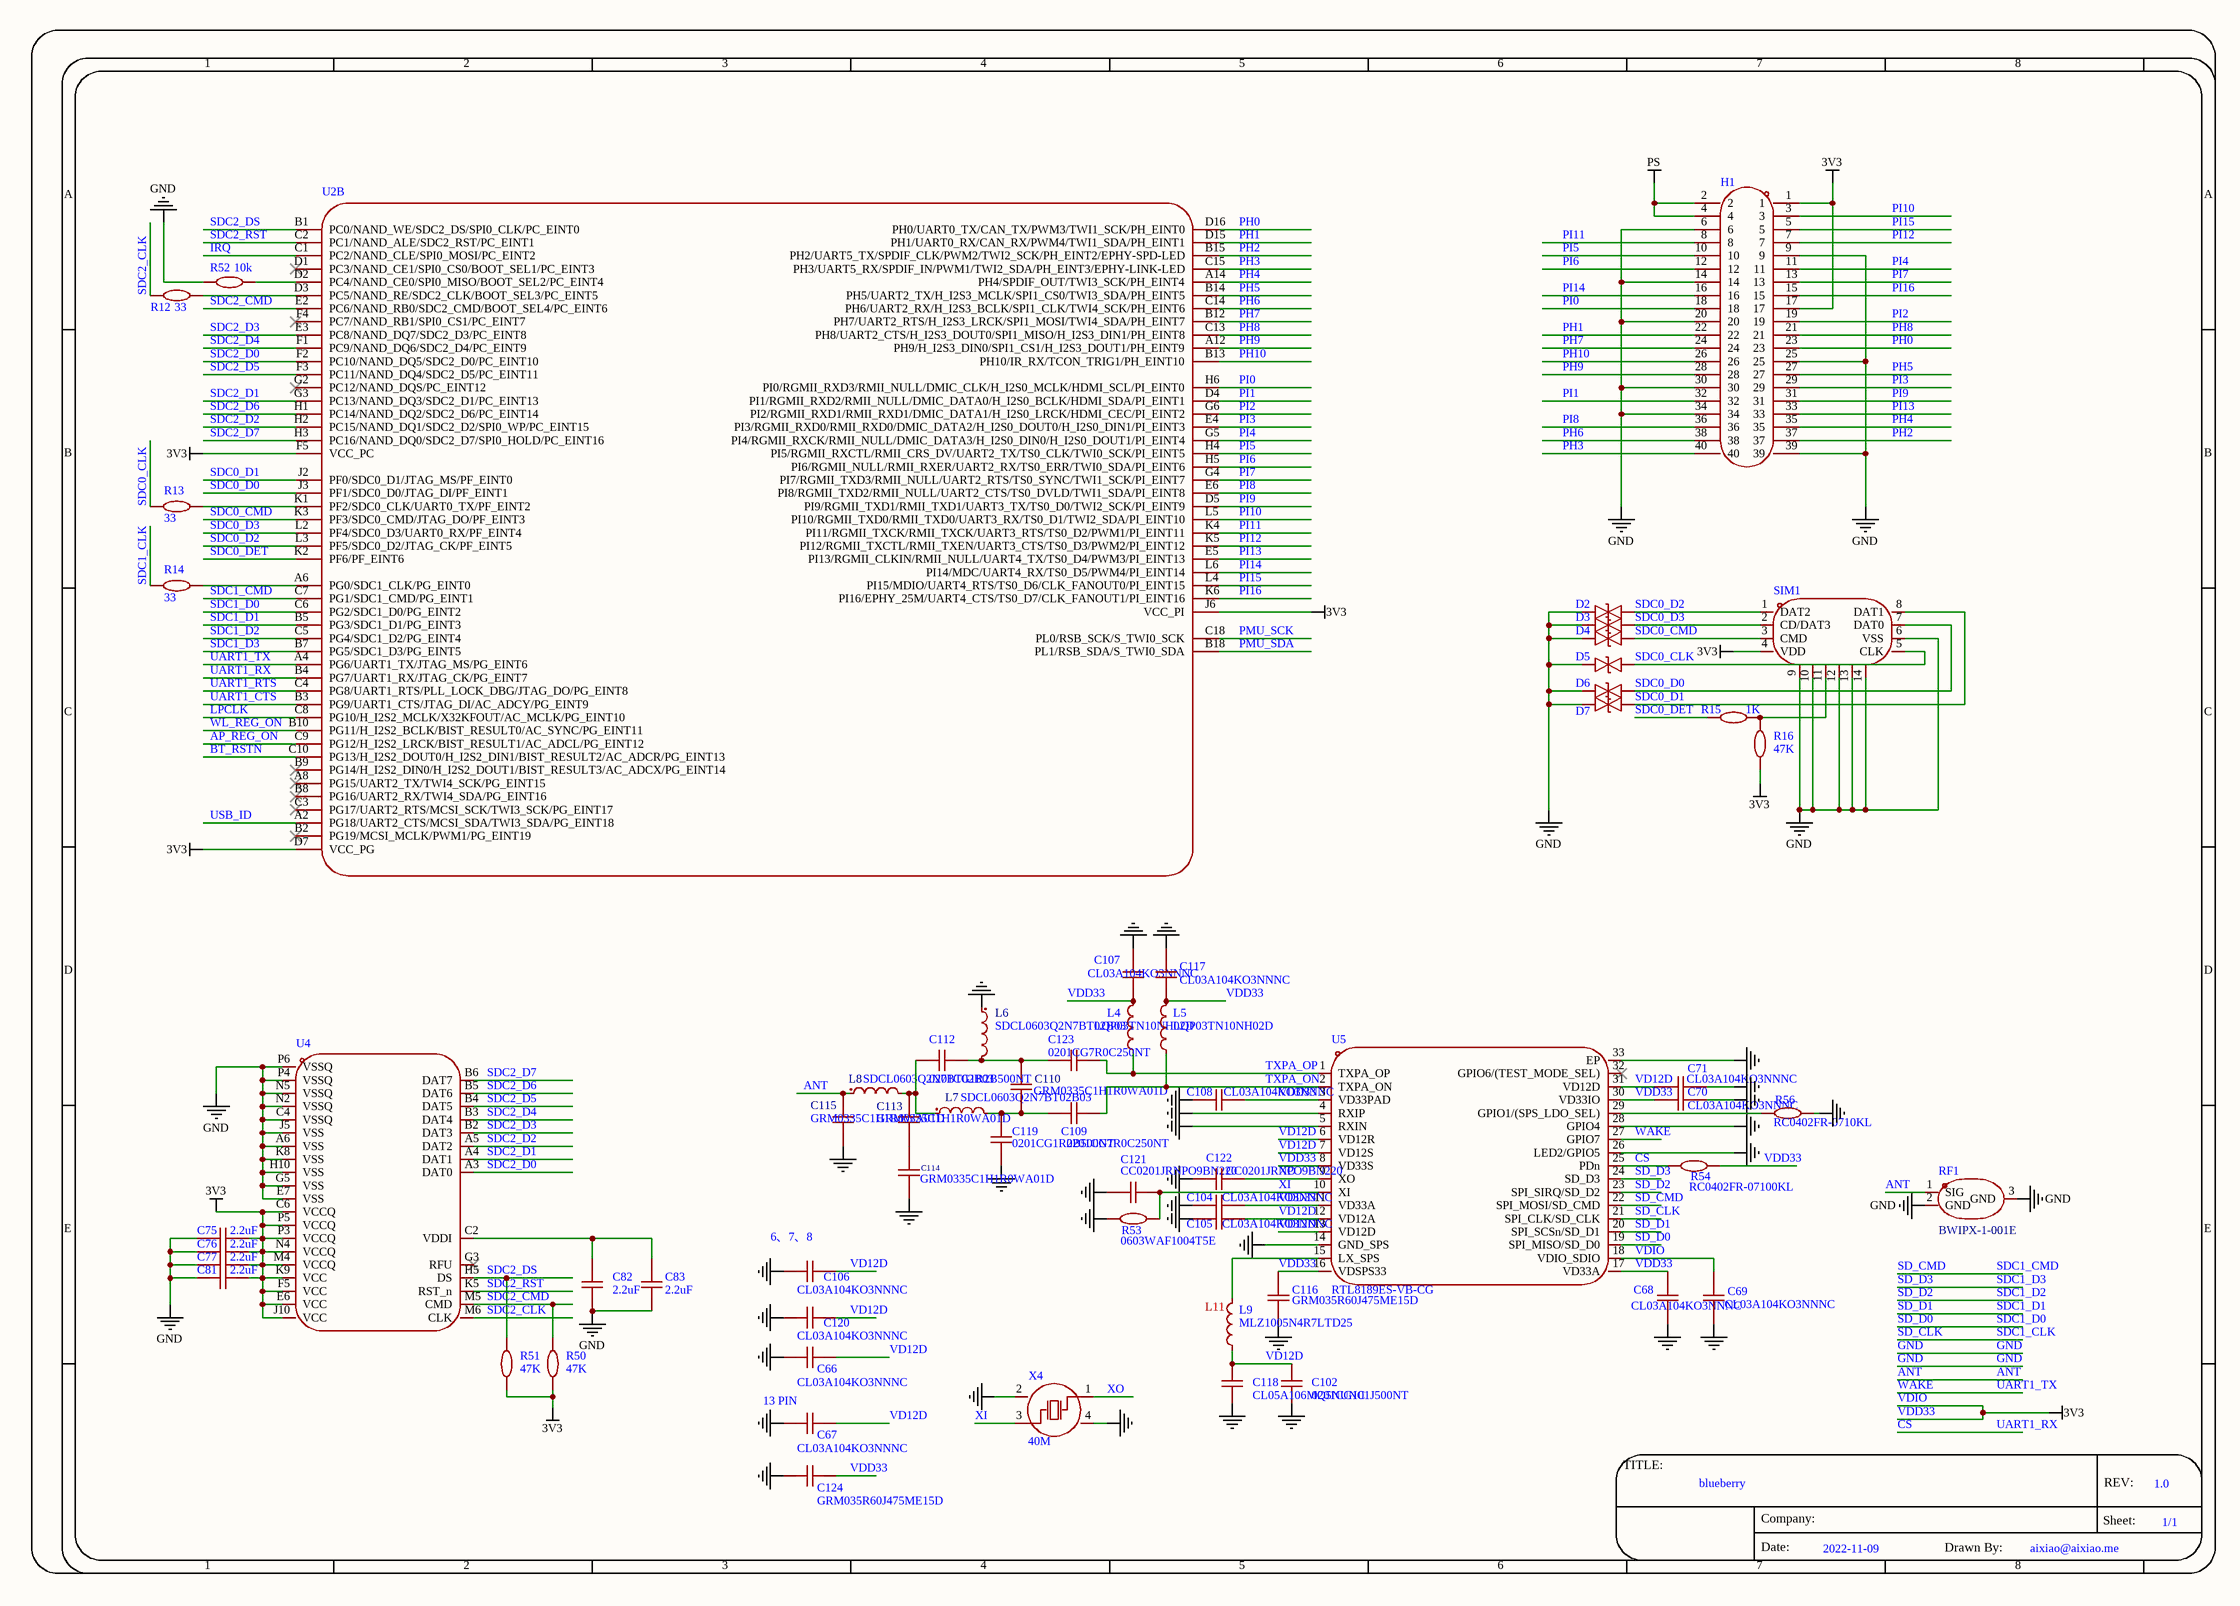
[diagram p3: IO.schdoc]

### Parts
C66  CL03A104KO3NNNC  [C0201]
C67  CL03A104KO3NNNC  [C0201]
C68  CL03A104KO3NNNC  [C0201]
C69  CL03A104KO3NNNC  [C0201]
C70  CL03A104KO3NNNC  [C0201]
C71  CL03A104KO3NNNC  [C0201]
C75  value 2.2uF  [C0402-NSK]  (hidden comment: CAP_0402)
C76  value 2.2uF  [C0402-NSK]  (hidden comment: CAP_0402)
C77  value 2.2uF  [C0402-NSK]  (hidden comment: CAP_0402)
C81  value 2.2uF  [C0402-NSK]  (hidden comment: CAP_0402)
C82  value 2.2uF  [C0402-NSK]  (hidden comment: CAP_0402)
C83  value 2.2uF  [C0402-NSK]  (hidden comment: CAP_0402)
C102  0201CG101J500NT  [C0201]
C104  CL03A104KO3NNNC  [C0201]
C105  CL03A104KO3NNNC  [C0201]
C106  CL03A104KO3NNNC  [C0201]
C107  CL03A104KO3NNNC  [C0201]
C108  CL03A104KO3NNNC  [C0201]
C109  0201CG7R0C250NT  [C0201]
C110  GRM0335C1H1R0WA01D  [C0201]
C112  0201CG1R2B500NT  [C0201]
C113  GRM0335C1H1R0WA01D  [C0201]
C114  GRM0335C1H1R0WA01D  [C0201]
C115  GRM0335C1H1R0WA01D  [C0201]
C116  GRM035R60J475ME15D  [C0201]
C117  CL03A104KO3NNNC  [C0201]
C118  CL05A106MQ5NUNC  [C0402]
C119  0201CG1R2B500NT  [C0201]
C120  CL03A104KO3NNNC  [C0201]
C121  CC0201JRNPO9BN220  [C0201]
C122  CC0201JRNPO9BN220  [C0201]
C123  0201CG7R0C250NT  [C0201]
C124  GRM035R60J475ME15D  [C0201]
D2  0402ESDA-05N  [D0402]  (value not drawn)
D3  0402ESDA-05N  [D0402]  (value not drawn)
D4  0402ESDA-05N  [D0402]  (value not drawn)
D5  0402ESDA-05N  [D0402]  (value not drawn)
D6  0402ESDA-05N  [D0402]  (value not drawn)
D7  0402ESDA-05N  [D0402]  (value not drawn)
H1  B-2100S40P-B110  [HDR-TH_40P-P2.54-V-M-R2-C20-S2.54]  (value not drawn)
L4  LQP03TN10NH02D  [L0201]
L5  LQP03TN10NH02D  [L0201]
L6  SDCL0603Q2N7BT02B03  [L0201-RD]
L7  SDCL0603Q2N7BT02B03  [L0201-RD]
L8  SDCL0603Q2N7BT02B03  [L0201-RD]
L9  MLZ1005N4R7LTD25  [L0402]
R12  value 33  [R0402-NSK_2]  (hidden comment: Res_0402)
R13  value 33  [R0402-NSK_2]  (hidden comment: Res_0402)
R14  value 33  [R0402-NSK_2]  (hidden comment: Res_0402)
R15  value 1K  [R0402-NSK_2]  (hidden comment: Res_0402)
R16  value 47K  [R0402-NSK_2]  (hidden comment: Res_0402)
R50  value 47K  [R0402-NSK_2]  (hidden comment: Res_0402)
R51  value 47K  [R0402-NSK_2]  (hidden comment: Res_0402)
R52  value 10k  [R0402-NSK_2]  (hidden comment: Res_0402)
R53  0603WAF1004T5E  [R0603]
R54  RC0402FR-07100KL  [R0402]
R56  RC0402FR-0710KL  [R0402]
RF1  BWIPX-1-001E  [IPEX-SMD_BWIPX-1-001E]
SIM1  1040310811  [SIM-SMD_8P-1040310811]  (value not drawn)
U2  Allwinner_H616  [BGA284P65B1200_1400H125]  (value not drawn)  (part B of 4)
U4  EMMC BGA153  [FBGA-153_L13.0-W11.5]  (value not drawn)
U5  RTL8189ES-VB-CG  [QFN-32_L5.0-W5.0-P0.50-TL-EP3.5]
X4  40M  [osc-smd_4p-l2.0-w1.6-bl]

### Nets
GND: C66.2 C67.2 C68.1 C69.1 C70.1 C71.1 C75.1 C76.1 C77.1 C81.1 C82.1 C83.1 C102.1 C104.2 C105.2 C106.2 C107.1 C108.2 C114.1 C115.1 C116.1 C117.1 C118.1 C119.2 C120.2 C121.2 C122.2 C124.2 D2.1 D3.1 D4.1 D5.1 D6.1 D7.1 H1.6 H1.9 H1.14 H1.20 H1.25 H1.30 H1.34 H1.39 L6.1 R52.2 R53.1 R56.2 RF1.2(GND) RF1.3(GND) SIM1.6(VSS) SIM1.9 SIM1.10 SIM1.12 SIM1.13 SIM1.14 U4.A6(VSS) U4.C4(VSSQ) U4.E7(VSS) U4.G5(VSS) U4.H10(VSS) U4.J5(VSS) U4.K8(VSS) U4.N2(VSSQ) U4.N5(VSSQ) U4.P4(VSSQ) U4.P6(VSSQ) U5.4(RXIP) U5.5(RXIN) U5.14(GND_SPS) U5.26(LED2/GPIO5) U5.28(GPIO4) U5.33(EP) X4.2(GND) X4.4(GND)
PS: H1.2 H1.4  [project net VBUS]
VDD33: C68.2 C69.2 C70.2 C75.2 C76.2 C77.2 C81.2 C104.1 C107.2 C108.1 C116.2 C117.2 C124.1 H1.1 H1.17 L4.2 L5.2 R16.1 R50.1 R51.1 R54.2 SIM1.4(VDD) U2.D7(VCC_PG) U2.F5(VCC_PC) U2.J6(VCC_PI) U4.C6(VCCQ) U4.E6(VCC) U4.F5(VCC) U4.J10(VCC) U4.K9(VCC) U4.M4(VCCQ) U4.N4(VCCQ) U4.P3(VCCQ) U4.P5(VCCQ) U5.3(VD33PAD) U5.8(VD33S) U5.11(VD33A) U5.16(VDSPS33) U5.17(VD33A) U5.18(VDIO_SDIO) U5.30(VD33IO)  [also labelled 3V3, VDIO]
ANT: C115.2 L8.1 RF1.1(SIG)
AP_REG_ON: U2.C9(PG12/H_I2S2_LRCK/BIST_RESULT1/AC_ADCL/PG_EINT12)
BT_RSTN: U2.C10(PG13/H_I2S2_DOUT0/H_I2S2_DIN1/BIST_RESULT2/AC_ADCR/PG_EINT13)
CS: R54.1 U2.B4(PG7/UART1_RX/JTAG_CK/PG_EINT7) U5.25(PDn)  [also labelled UART1_RX]
IRQ: U2.C1(PC2/NAND_CLE/SPI0_MOSI/PC_EINT2)
LPCLK: U2.C8(PG10/H_I2S2_MCLK/X32KFOUT/AC_MCLK/PG_EINT10)
PH0: H1.23 U2.D16(PH0/UART0_TX/CAN_TX/PWM3/TWI1_SCK/PH_EINT0)
PH1: H1.22 U2.D15(PH1/UART0_RX/CAN_RX/PWM4/TWI1_SDA/PH_EINT1)
PH2: H1.37 U2.B15(PH2/UART5_TX/SPDIF_CLK/PWM2/TWI2_SCK/PH_EINT2/EPHY-SPD-LED)
PH3: H1.40 U2.C15(PH3/UART5_RX/SPDIF_IN/PWM1/TWI2_SDA/PH_EINT3/EPHY-LINK-LED)
PH4: H1.35 U2.A14(PH4/SPDIF_OUT/TWI3_SCK/PH_EINT4)
PH5: H1.27 U2.B14(PH5/UART2_TX/H_I2S3_MCLK/SPI1_CS0/TWI3_SDA/PH_EINT5)
PH6: H1.38 U2.C14(PH6/UART2_RX/H_I2S3_BCLK/SPI1_CLK/TWI4_SCK/PH_EINT6)
PH7: H1.24 U2.B12(PH7/UART2_RTS/H_I2S3_LRCK/SPI1_MOSI/TWI4_SDA/PH_EINT7)
PH8: H1.21 U2.C13(PH8/UART2_CTS/H_I2S3_DOUT0/SPI1_MISO/H_I2S3_DIN1/PH_EINT8)
PH9: H1.28 U2.A12(PH9/H_I2S3_DIN0/SPI1_CS1/H_I2S3_DOUT1/PH_EINT9)
PH10: H1.26 U2.B13(PH10/IR_RX/TCON_TRIG1/PH_EINT10)
PI0: H1.18 U2.H6(PI0/RGMII_RXD3/RMII_NULL/DMIC_CLK/H_I2S0_MCLK/HDMI_SCL/PI_EINT0)
PI1: H1.32 U2.D4(PI1/RGMII_RXD2/RMII_NULL/DMIC_DATA0/H_I2S0_BCLK/HDMI_SDA/PI_EINT1)
PI2: H1.19 U2.G6(PI2/RGMII_RXD1/RMII_RXD1/DMIC_DATA1/H_I2S0_LRCK/HDMI_CEC/PI_EINT2)
PI3: H1.29 U2.E4(PI3/RGMII_RXD0/RMII_RXD0/DMIC_DATA2/H_I2S0_DOUT0/H_I2S0_DIN1/PI_EINT3)
PI4: H1.11 U2.G5(PI4/RGMII_RXCK/RMII_NULL/DMIC_DATA3/H_I2S0_DIN0/H_I2S0_DOUT1/PI_EINT4)
PI5: H1.10 U2.H4(PI5/RGMII_RXCTL/RMII_CRS_DV/UART2_TX/TS0_CLK/TWI0_SCK/PI_EINT5)
PI6: H1.12 U2.H5(PI6/RGMII_NULL/RMII_RXER/UART2_RX/TS0_ERR/TWI0_SDA/PI_EINT6)
PI7: H1.13 U2.G4(PI7/RGMII_TXD3/RMII_NULL/UART2_RTS/TS0_SYNC/TWI1_SCK/PI_EINT7)
PI8: H1.36 U2.E6(PI8/RGMII_TXD2/RMII_NULL/UART2_CTS/TS0_DVLD/TWI1_SDA/PI_EINT8)
PI9: H1.31 U2.D5(PI9/RGMII_TXD1/RMII_TXD1/UART3_TX/TS0_D0/TWI2_SCK/PI_EINT9)
PI10: H1.3 U2.L5(PI10/RGMII_TXD0/RMII_TXD0/UART3_RX/TS0_D1/TWI2_SDA/PI_EINT10)
PI11: H1.8 U2.K4(PI11/RGMII_TXCK/RMII_TXCK/UART3_RTS/TS0_D2/PWM1/PI_EINT11)
PI12: H1.7 U2.K5(PI12/RGMII_TXCTL/RMII_TXEN/UART3_CTS/TS0_D3/PWM2/PI_EINT12)
PI13: H1.33 U2.E5(PI13/RGMII_CLKIN/RMII_NULL/UART4_TX/TS0_D4/PWM3/PI_EINT13)
PI14: H1.16 U2.L6(PI14/MDC/UART4_RX/TS0_D5/PWM4/PI_EINT14)
PI15: H1.5 U2.L4(PI15/MDIO/UART4_RTS/TS0_D6/CLK_FANOUT0/PI_EINT15)
PI16: H1.15 U2.K6(PI16/EPHY_25M/UART4_CTS/TS0_D7/CLK_FANOUT1/PI_EINT16)
PMU_SCK: U2.C18(PL0/RSB_SCK/S_TWI0_SCK)
PMU_SDA: U2.B18(PL1/RSB_SDA/S_TWI0_SDA)
SD_CLK: R14.1 U5.21(SPI_CLK/SD_CLK)  [also labelled SDC1_CLK]
SD_CMD: U2.C7(PG1/SDC1_CMD/PG_EINT1) U5.22(SPI_MOSI/SD_CMD)  [also labelled SDC1_CMD]
SD_D0: U2.C6(PG2/SDC1_D0/PG_EINT2) U5.19(SPI_MISO/SD_D0)  [also labelled SDC1_D0]
SD_D1: U2.B5(PG3/SDC1_D1/PG_EINT3) U5.20(SPI_SCSn/SD_D1)  [also labelled SDC1_D1]
SD_D2: U2.C5(PG4/SDC1_D2/PG_EINT4) U5.23(SPI_SIRQ/SD_D2)  [also labelled SDC1_D2]
SD_D3: U2.B7(PG5/SDC1_D3/PG_EINT5) U5.24(SD_D3)  [also labelled SDC1_D3]
SDC0_CLK: D5.2 R13.1 SIM1.5(CLK)
SDC0_CMD: D4.2 SIM1.3(CMD) U2.K3(PF3/SDC0_CMD/JTAG_DO/PF_EINT3)
SDC0_D0: D6.2 SIM1.7(DAT0) U2.J3(PF1/SDC0_D0/JTAG_DI/PF_EINT1)
SDC0_D1: D7.2 SIM1.8(DAT1) U2.J2(PF0/SDC0_D1/JTAG_MS/PF_EINT0)
SDC0_D2: D2.2 SIM1.1(DAT2) U2.L3(PF5/SDC0_D2/JTAG_CK/PF_EINT5)
SDC0_D3: D3.2 SIM1.2(CD/DAT3) U2.L2(PF4/SDC0_D3/UART0_RX/PF_EINT4)
SDC0_DET: R15.1 U2.K2(PF6/PF_EINT6)
SDC2_CLK: R12.1 U4.M6(CLK)
SDC2_CMD: R50.2 U2.E2(PC6/NAND_RB0/SDC2_CMD/BOOT_SEL4/PC_EINT6) U4.M5(CMD)
SDC2_D0: U2.F2(PC10/NAND_DQ5/SDC2_D0/PC_EINT10) U4.A3(DAT0)
SDC2_D1: U2.G3(PC13/NAND_DQ3/SDC2_D1/PC_EINT13) U4.A4(DAT1)
SDC2_D2: U2.H2(PC15/NAND_DQ1/SDC2_D2/SPI0_WP/PC_EINT15) U4.A5(DAT2)
SDC2_D3: U2.E3(PC8/NAND_DQ7/SDC2_D3/PC_EINT8) U4.B2(DAT3)
SDC2_D4: U2.F1(PC9/NAND_DQ6/SDC2_D4/PC_EINT9) U4.B3(DAT4)
SDC2_D5: U2.F3(PC11/NAND_DQ4/SDC2_D5/PC_EINT11) U4.B4(DAT5)
SDC2_D6: U2.H1(PC14/NAND_DQ2/SDC2_D6/PC_EINT14) U4.B5(DAT6)
SDC2_D7: U2.H3(PC16/NAND_DQ0/SDC2_D7/SPI0_HOLD/PC_EINT16) U4.B6(DAT7)
SDC2_DS: R51.2 U2.B1(PC0/NAND_WE/SDC2_DS/SPI0_CLK/PC_EINT0) U4.H5(DS)
SDC2_RST: U2.C2(PC1/NAND_ALE/SDC2_RST/PC_EINT1) U4.K5(RST_n)
TXPA_ON: C109.2 L5.1 U5.2(TXPA_ON)
TXPA_OP: C123.2 L4.1 U5.1(TXPA_OP)
UART1_CTS: U2.B3(PG9/UART1_CTS/JTAG_DI/AC_ADCY/PG_EINT9)
UART1_RTS: U2.C4(PG8/UART1_RTS/PLL_LOCK_DBG/JTAG_DO/PG_EINT8)
UART1_TX: U2.A4(PG6/UART1_TX/JTAG_MS/PG_EINT6) U5.27(GPIO7)  [also labelled WAKE]
USB_ID: U2.A2(PG18/UART2_CTS/MCSI_SDA/TWI3_SDA/PG_EINT18)
VD12D: C66.1 C67.1 C71.2 C102.2 C105.1 C106.1 C118.2 C120.1 L9.1 U5.6(VD12R) U5.7(VD12S) U5.12(VD12A) U5.13(VD12D) U5.31(VD12D)
WL_REG_ON: U2.B10(PG11/H_I2S2_BCLK/BIST_RESULT0/AC_SYNC/PG_EINT11)
XI: C121.1 R53.2 U5.10(XI) X4.3(OSC2)
XO: C122.1 U5.9(XO) X4.1(OSC1)
NetC82_2: C82.2 C83.2 U4.C2(VDDI)
NetC109_1: C109.1 C110.1 C119.1 L7.2
NetC110_2: C110.2 C112.1 C123.1 L6.2
NetC112_2: C112.2 C113.2 L7.1 L8.2
NetC113_1: C113.1 C114.2
NetL9_2: L9.2 U5.15(LX_SPS)
NetR12_2: R12.2 U2.D3(PC5/NAND_RE/SDC2_CLK/BOOT_SEL3/PC_EINT5)
NetR13_2: R13.2 U2.K1(PF2/SDC0_CLK/UART0_TX/PF_EINT2)
NetR14_2: R14.2 U2.A6(PG0/SDC1_CLK/PG_EINT0)
NetR15_2: R15.2 R16.2 SIM1.11
NetR52_1: R52.1 U2.D2(PC4/NAND_CE0/SPI0_MISO/BOOT_SEL2/PC_EINT4)
NetR56_1: R56.1 U5.29(GPIO1/(SPS_LDO_SEL))

Not connected (* = marked no-connect by the designer): U2 A8(PG15/UART2_TX/TWI4_SCK/PG_EINT15)* B2(PG19/MCSI_MCLK/PWM1/PG_EINT19)* B8(PG16/UART2_RX/TWI4_SDA/PG_EINT16)* B9(PG14/H_I2S2_DIN0/H_I2S2_DOUT1/BIST_RESULT3/AC_ADCX/PG_EINT14)* C3(PG17/UART2_RTS/MCSI_SCK/TWI3_SCK/PG_EINT17)* D1(PC3/NAND_CE1/SPI0_CS0/BOOT_SEL1/PC_EINT3)* F4(PC7/NAND_RB1/SPI0_CS1/PC_EINT7)* G2(PC12/NAND_DQS/PC_EINT12)*; U4 G3(RFU)*; U5 32(GPIO6/(TEST_MODE_SEL))*

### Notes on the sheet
- (near C106) 6、7、8
- (near L9) L11
- (near C67) 13 PIN

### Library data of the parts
C66-C71 C104-C108 C117 C120 = CL03A104KO3NNNC: Manufacturer: SAMSUNG(三星); Add into BOM: yes; Value: 100nF; Tolerance: ±10%; Voltage Rated: 16V; Temperature Coefficient: X5R
C75-C77 C81-C83 = CAP_0402: as C1 on sheet POWER
C102 = 0201CG101J500NT: Manufacturer: FH(风华); Add into BOM: yes; Value: 100pF; Tolerance: ±5%; Voltage Rated: 50V; Temperature Coefficient: C0G
C109 C123 = 0201CG7R0C250NT: Manufacturer: FH(风华); Add into BOM: yes; Value: 7pF; Voltage Rated: 25V; Temperature Coefficient: C0G
C110 C113-C115 = GRM0335C1H1R0WA01D: Manufacturer: muRata(村田); Value: 1pF; Add into BOM: yes; Voltage Rated: 50V; Temperature Coefficient: C0G
C112 C119 = 0201CG1R2B500NT: Manufacturer: FH(风华); Add into BOM: yes; Value: 1.2pF; Voltage Rated: 50V; Temperature Coefficient: C0G
C116 C124 = GRM035R60J475ME15D: Manufacturer: muRata(村田); Add into BOM: yes; Value: 4.7uF; Tolerance: ±20%; Voltage Rated: 6.3V; Temperature Coefficient: X5R
C118 = CL05A106MQ5NUNC: Manufacturer: SAMSUNG(三星); Add into BOM: yes; Value: 10uF; Tolerance: ±20%; Voltage Rated: 6.3V; Temperature Coefficient: X5R
C121 C122 = CC0201JRNPO9BN220: Manufacturer: YAGEO(国巨); Add into BOM: yes; Value: 22pF; Tolerance: ±5%; Voltage Rated: 50V; Temperature Coefficient: NP0
D2-D7 = 0402ESDA-05N: as D8 on sheet PLL-IO
H1 = B-2100S40P-B110: Manufacturer: Ckmtw(灿科盟); Symbol: 210S-2*20P L=11.6MMGold-plated black; Add into BOM: yes; Pitch: 2.54mm; Pin Structure: 2x20P
L4 L5 = LQP03TN10NH02D: Manufacturer: muRata(村田); Add into BOM: yes; Value: 10nH; Tolerance: ±3%; Rated Current: 250mA; DC Resistance (DCR): 700mΩ; Q @ Freq: 14@500MHz; Frequency - Self Resonant: 3.2GHz
L6-L8 = SDCL0603Q2N7BT02B03: Manufacturer: Sunlord(顺络); Value: 2.7nH; Add into BOM: yes; Rated Current: 500mA; DC Resistance (DCR): 200mΩ; Q @ Freq: 13@500MHz; Frequency - Self Resonant: 500MHz
L9 = MLZ1005N4R7LTD25: Manufacturer: TDK; Add into BOM: yes; Value: 4.7uH; Tolerance: ±20%
R12-R16 R50-R52 = Res_0402: Symbol: 电阻; Convert to PCB: yes
R53 = 0603WAF1004T5E: Manufacturer: UNI-ROYAL(厚声); Add into BOM: yes; Value: 1MΩ; Tolerance: ±1%; Power(Watts): 100mW; Temperature Coefficient: ±100ppm/℃; Overload Voltage (Max): 75V
R54 = RC0402FR-07100KL: Manufacturer: YAGEO(国巨); Add into BOM: yes; Value: 100kΩ; Tolerance: ±1%; Power(Watts): 62.5mW; Temperature Coefficient: ±100ppm/℃; Overload Voltage (Max): 50V
R56 = RC0402FR-0710KL: Manufacturer: YAGEO(国巨); Add into BOM: yes; Value: 10kΩ; Tolerance: ±1%; Power(Watts): 62.5mW; Temperature Coefficient: ±100ppm/℃; Overload Voltage (Max): 50V
RF1 = BWIPX-1-001E: Manufacturer: BATWIRELESS(蝙蝠无线); Add into BOM: yes; Connector Type: 板端; RF Series: IPEX; Interface Type: 内针; Number of Ports: 1; Impedance: 50Ω; Frequency-Max: 6GHz
SIM1 = 1040310811: Manufacturer: MOLEX; Add into BOM: yes; Card Connection Mode: 拔插式; Card Type: MicroSD卡(TF卡); Connector Type: 卡座; Maximum Body Height: 1.42mm
U2 = Allwinner_H616: as U2 on sheet POWER
U4 = EMMC BGA153: Manufacturer: Kingston(金士顿); Manufacturer Part: EMMC04G-M627-A01; Pin Type: IN; Add into BOM: yes
U5 = RTL8189ES-VB-CG: Manufacturer: REALTEK(瑞昱); Add into BOM: yes
X4 = SX32Y024000BC1T: Manufacturer: TKD(泰晶); Add into BOM: yes

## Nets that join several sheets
1V8: POWER (8 pins), PLL-IO (6 pins), DRAM (U2.L14)
GND: POWER (93 pins), PLL-IO (78 pins), DRAM (61 pins), IO (73 pins)
VBUS: POWER (7 pins), PLL-IO (9 pins), IO (H1.2 H1.4)
VCC_DRAM: POWER (8 pins), DRAM (57 pins)
VDD33: POWER (8 pins), PLL-IO (D23.2 R33.2 U2.E18 U2.M18), IO (41 pins)
IRQ: POWER (R4.1), IO (U2.C1)
PMU_SCK: POWER (R3.2 U1.6), IO (U2.C18)
PMU_SDA: POWER (R2.2 U1.5), IO (U2.B18)
RESET: POWER (C100.2 R5.1 R49.1), PLL-IO (R28.1 U2.A16)
USB_ID: PLL-IO (R34.1), IO (U2.A2)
